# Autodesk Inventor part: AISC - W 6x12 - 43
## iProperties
Created: 2004-08
Part Number: AISC - W 6x12 - 43
Material: Steel, Mild
Vendor: Autodesk Inc.
Document SubType Name: Modeling
Designer: John Blackburn
Description: W Shape
Standard: AISC
Size Designation: W 6x12 - 43
Control State: 0
Master: False
Checked Out: False
Shininess: 64.0
Length Units: 11272
Angle Units: 11279
Time Units: 11290
Mass Units: 11286
Length Display Precision: 3
Angle Display Precision: 2
Density: 0.0
Volumn: 0.0
Area: 0.0
PropertySet Name: Model Information
Author: John Blackburn
Revision Number: 8
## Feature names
1. Body [Extrusion]
2. Fillet1
